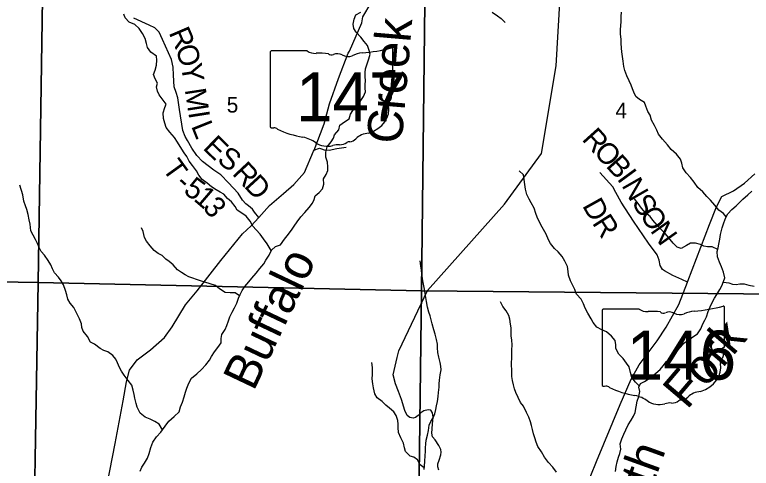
# Model space of a CAD drawing. Extents: x 2043100 to 2470832, y 443715 to 810583.
# Drawn here: x 2263711 to 2274168, y 662503 to 668947 of the extents above; entities that cross this region are included whole.
import ezdxf

# ---------------------------------------------------------------- set-up
doc = ezdxf.new("R2010")
doc.units = 0
for name, color, linetype in [('GM_X_Minor_River', 7, 'Continuous'), ('GM_X_Minor_River_Text', 7, 'Continuous'), ('GM_X_Section', 7, 'Continuous'), ('GM_X_Section_Text', 7, 'Continuous'), ('GM_X_State_Location', 7, 'Continuous'), ('GM_X_State_Route', 7, 'Continuous'), ('GM_X_State_Shield', 7, 'Continuous'), ('GM_X_Township_Road', 7, 'Continuous'), ('GM_X_Township_Road_Text', 7, 'Continuous'), ('GM_X_Township_ROW', 7, 'Continuous')]:
    doc.layers.add(name, color=color, linetype=linetype)

msp = doc.modelspace()

# ---------------------------------------------------------------- linework, layer by layer
at = {"layer": 'GM_X_Minor_River'}
for points in [[(2267354, 665598), (2267295, 665691), (2267242, 665765), (2267196, 665827), (2267137, 665892), (2267092, 665944), (2267052, 666013), (2266999, 666083), (2266935, 666128), (2266868, 666170), (2266842, 666224), (2266791, 666289), (2266732, 666335), (2266678, 666398), (2266626, 666428), (2266569, 666459), (2266507, 666503), (2266442, 666554), (2266374, 666607), (2266325, 666669), (2266293, 666727), (2266236, 666804), (2266189, 666864), (2266154, 666932), (2266116, 666983), (2266061, 667073), (2266024, 667135), (2265980, 667202), (2265911, 667278), (2265862, 667343), (2265842, 667407), (2265823, 667471), (2265820, 667555), (2265841, 667627), (2265859, 667678), (2265762, 667809), (2265739, 667863), (2265724, 667921), (2265738, 667973), (2265703, 668037), (2265683, 668098), (2265704, 668157), (2265723, 668231), (2265728, 668301), (2265726, 668359), (2265645, 668413), (2265597, 668482), (2265582, 668536), (2265561, 668608), (2265527, 668678), (2265478, 668753), (2265415, 668807), (2265337, 668842), (2265280, 668901), (2265262, 668955)], [(2267678, 665942), (2267722, 666006), (2267775, 666075), (2267832, 666138), (2267889, 666206), (2267941, 666271), (2267962, 666321), (2267978, 666374), (2268035, 666422), (2268079, 666475), (2268098, 666541), (2268095, 666613), (2268133, 666676), (2268158, 666732), (2268155, 666784), (2268153, 666850), (2268130, 666922), (2268127, 666992), (2268146, 667070), (2268206, 667139), (2268235, 667192), (2268253, 667242), (2268314, 667312), (2268329, 667377), (2268393, 667423), (2268458, 667470), (2268480, 667535), (2268511, 667587), (2268568, 667656), (2268614, 667716), (2268661, 667783), (2268690, 667851), (2268686, 667903), (2268685, 667953), (2268693, 668013), (2268688, 668066), (2268684, 668124), (2268691, 668176), (2268712, 668236), (2268737, 668322), (2268755, 668385), (2268744, 668437), (2268720, 668508), (2268671, 668568), (2268624, 668630), (2268558, 668699), (2268525, 668751), (2268516, 668813), (2268528, 668883), (2268553, 668945), (2268623, 668982)], [(2270490, 668984), (2270567, 668930), (2270619, 668895), (2270672, 668837)], [(2273811, 666077), (2273773, 666123), (2273708, 666172), (2273651, 666242), (2273591, 666311), (2273538, 666365), (2273481, 666432), (2273411, 666494), (2273358, 666567), (2273303, 666635), (2273243, 666702), (2273196, 666770), (2273183, 666840), (2273165, 666896), (2273108, 666967), (2273033, 667031), (2272977, 667100), (2272906, 667178), (2272851, 667251), (2272825, 667307), (2272794, 667375), (2272753, 667451), (2272732, 667522), (2272698, 667574), (2272671, 667646), (2272651, 667698), (2272582, 667743), (2272528, 667785), (2272499, 667845), (2272481, 667896), (2272462, 667948), (2272436, 668010), (2272403, 668078), (2272372, 668156), (2272358, 668212), (2272349, 668286), (2272338, 668352), (2272329, 668418), (2272325, 668472), (2272320, 668544), (2272320, 668594), (2272309, 668676), (2272310, 668730), (2272321, 668850), (2272322, 668924), (2272324, 668982)], [(2272580, 663669), (2272526, 663726), (2272471, 663795), (2272454, 663865), (2272433, 663943), (2272397, 663995), (2272350, 664063), (2272290, 664122), (2272245, 664204), (2272244, 664258), (2272236, 664316), (2272183, 664382), (2272114, 664443), (2272046, 664468), (2271976, 664506), (2271923, 664573), (2271895, 664627), (2271846, 664705), (2271811, 664776), (2271786, 664838), (2271752, 664904), (2271689, 664976), (2271662, 665043), (2271632, 665111), (2271603, 665167), (2271574, 665245), (2271570, 665299), (2271557, 665371), (2271520, 665447), (2271482, 665514), (2271427, 665580), (2271376, 665625), (2271316, 665697), (2271289, 665749), (2271256, 665831), (2271220, 665896), (2271179, 665962), (2271126, 666070), (2271111, 666124), (2271085, 666197), (2271044, 666273), (2271015, 666327), (2270981, 666393), (2270964, 666469), (2270951, 666537), (2270944, 666605), (2270932, 666673), (2270873, 666730)], [(2265808, 663049), (2265760, 663129), (2265698, 663167), (2265633, 663202), (2265561, 663228), (2265494, 663285), (2265450, 663369), (2265433, 663425), (2265418, 663497), (2265408, 663551), (2265395, 663611), (2265372, 663684), (2265320, 663750), (2265265, 663828), (2265226, 663881), (2265198, 663933), (2265169, 663999), (2265145, 664053), (2265102, 664104), (2265033, 664158), (2264977, 664177), (2264925, 664207), (2264846, 664268), (2264786, 664297), (2264743, 664373), (2264685, 664449), (2264662, 664505), (2264657, 664555), (2264629, 664624), (2264590, 664710), (2264551, 664788), (2264500, 664851), (2264466, 664905), (2264451, 664967), (2264431, 665027), (2264402, 665107), (2264371, 665165), (2264333, 665216), (2264278, 665278), (2264246, 665336), (2264223, 665393), (2264186, 665455), (2264132, 665531), (2264087, 665582), (2264056, 665638), (2264034, 665698), (2264005, 665754), (2263971, 665814), (2263940, 665875), (2263931, 665973), (2263918, 666033), (2263900, 666107), (2263883, 666179), (2263864, 666231), (2263840, 666299), (2263825, 666387), (2263783, 666523)], [(2272241, 662459), (2272250, 662527), (2272265, 662593), (2272283, 662661), (2272304, 662714), (2272314, 662776), (2272305, 662852), (2272328, 662920), (2272359, 662989), (2272389, 663049), (2272418, 663118), (2272465, 663188), (2272497, 663245), (2272520, 663297), (2272533, 663375), (2272548, 663458), (2272570, 663524), (2272585, 663594), (2272574, 663656), (2272596, 663707), (2272652, 663735), (2272705, 663770), (2272763, 663812), (2272814, 663853), (2272876, 663904), (2272917, 663958), (2272964, 664021), (2273016, 664068), (2273067, 664118), (2273117, 664171), (2273170, 664229), (2273212, 664280), (2273265, 664317), (2273337, 664371), (2273404, 664414), (2273450, 664483), (2273479, 664553), (2273508, 664606), (2273530, 664656), (2273555, 664732), (2273582, 664795), (2273608, 664847), (2273647, 664920), (2273678, 664972), (2273720, 665041), (2273749, 665097), (2273776, 665155), (2273792, 665208), (2273773, 665290), (2273746, 665363), (2273716, 665429), (2273687, 665505), (2273686, 665583), (2273698, 665637), (2273707, 665688), (2273722, 665756), (2273732, 665824), (2273753, 665918), (2273778, 665989), (2273805, 666065), (2273833, 666116), (2273890, 666178), (2273953, 666233), (2274050, 666326), (2274120, 666389), (2274177, 666442)], [(2273692, 665610), (2273615, 665649), (2273547, 665650), (2273495, 665657), (2273445, 665683), (2273377, 665700), (2273303, 665699), (2273247, 665667), (2273172, 665626), (2273114, 665643), (2273061, 665701), (2272952, 665832), (2272889, 665897), (2272833, 665957), (2272772, 666028), (2272731, 666080), (2272665, 666134), (2272610, 666199), (2272563, 666265), (2272511, 666330)], [(2265491, 662464), (2265514, 662520), (2265552, 662576), (2265595, 662647), (2265620, 662713), (2265645, 662798), (2265671, 662872), (2265722, 662949), (2265785, 663017), (2265846, 663102), (2265901, 663171), (2265975, 663240), (2266046, 663303), (2266065, 663375), (2266093, 663443), (2266118, 663516), (2266137, 663584), (2266156, 663640), (2266184, 663713), (2266221, 663785), (2266298, 663846), (2266362, 663907), (2266425, 663972), (2266474, 664040), (2266506, 664091), (2266549, 664159), (2266594, 664220), (2266642, 664284), (2266643, 664349), (2266652, 664403), (2266698, 664473), (2266721, 664530), (2266744, 664600), (2266764, 664654), (2266797, 664721), (2266832, 664783), (2266866, 664850), (2266887, 664920), (2266911, 664970), (2266942, 665031), (2266977, 665087), (2267035, 665154), (2267076, 665204), (2267139, 665273), (2267189, 665342), (2267246, 665408), (2267277, 665461), (2267323, 665533), (2267356, 665602), (2267415, 665655), (2267483, 665679), (2267540, 665756), (2267580, 665807), (2267639, 665885), (2267678, 665942)], [(2266902, 664951), (2266842, 664996), (2266772, 664995), (2266698, 665002), (2266620, 665051), (2266561, 665101), (2266487, 665124), (2266409, 665147), (2266347, 665165), (2266292, 665184), (2266240, 665202), (2266184, 665225), (2266132, 665249), (2266080, 665284), (2266021, 665324), (2265960, 665393), (2265906, 665443), (2265856, 665476), (2265805, 665524), (2265747, 665553), (2265692, 665599), (2265634, 665662), (2265581, 665732), (2265555, 665784), (2265534, 665866), (2265511, 665917)], [(2269523, 662485), (2269529, 662539), (2269532, 662599), (2269539, 662685), (2269541, 662742), (2269542, 662794), (2269546, 662850), (2269553, 662900), (2269572, 662972), (2269586, 663042), (2269595, 663117), (2269620, 663167), (2269652, 663220), (2269675, 663276), (2269691, 663338), (2269698, 663392), (2269711, 663453), (2269721, 663521), (2269728, 663579), (2269735, 663653), (2269739, 663703), (2269742, 663755), (2269753, 663830), (2269763, 663902), (2269760, 663956), (2269752, 664008), (2269731, 664080), (2269716, 664150), (2269714, 664212), (2269711, 664264), (2269700, 664334), (2269680, 664406), (2269659, 664472), (2269636, 664556), (2269623, 664610), (2269611, 664668), (2269592, 664720), (2269572, 664791), (2269555, 664871), (2269546, 664929), (2269536, 664985), (2269527, 665049), (2269510, 665143), (2269499, 665197), (2269491, 665265), (2269484, 665319), (2269476, 665381), (2269467, 665451)], [(2273773, 665149), (2273849, 665138), (2273901, 665119), (2273953, 665113), (2274007, 665122), (2274065, 665124), (2274131, 665105), (2274207, 665090)], [(2271405, 662450), (2271353, 662518), (2271290, 662583), (2271233, 662663), (2271188, 662736), (2271140, 662814), (2271115, 662874), (2271094, 662934), (2271076, 662994), (2271063, 663056), (2271048, 663110), (2271032, 663162), (2271009, 663231), (2270979, 663295), (2270932, 663385), (2270893, 663439), (2270858, 663510), (2270826, 663578), (2270807, 663632), (2270791, 663688), (2270778, 663752), (2270769, 663806), (2270767, 663874), (2270765, 663998), (2270767, 664070), (2270768, 664123), (2270769, 664183), (2270773, 664257), (2270768, 664321), (2270761, 664383), (2270760, 664497), (2270750, 664551), (2270739, 664621), (2270726, 664675), (2270690, 664741), (2270639, 664802), (2270606, 664870)], [(2269526, 662507), (2269465, 662554), (2269428, 662624), (2269378, 662662), (2269323, 662677), (2269261, 662741), (2269246, 662793), (2269230, 662859), (2269193, 662934), (2269160, 663012), (2269155, 663080), (2269155, 663130), (2269150, 663180), (2269126, 663254), (2269093, 663306), (2269031, 663355), (2268980, 663401), (2268926, 663454), (2268857, 663504), (2268822, 663562), (2268804, 663646), (2268795, 663702), (2268788, 663772), (2268790, 663836), (2268791, 663886), (2268789, 663936), (2268780, 664004)]]:
    msp.add_lwpolyline(points, dxfattribs=at)
at = {"layer": 'GM_X_Section'}
for points in [[(2264125, 670418), (2264045, 665142), (2258605, 665232), (2258713, 670510)], [(2264693, 670424), (2269548, 670345), (2269488, 665022), (2264045, 665142), (2264125, 670418)], [(2269548, 670345), (2269964, 670340), (2275177, 670269), (2275075, 664974), (2269488, 665022)], [(2264045, 665142), (2263953, 659859), (2258515, 659943), (2258605, 665232)], [(2264045, 665142), (2269488, 665022), (2269418, 659783), (2263953, 659859)], [(2275075, 664974), (2274869, 659715), (2269418, 659783), (2269488, 665022)]]:
    msp.add_lwpolyline(points, close=True, dxfattribs=at)
at = {"layer": 'GM_X_State_Route'}
for points in [[(2264990, 662104), (2265135, 662857), (2265250, 663463), (2265298, 663730), (2265339, 663897), (2265450, 664046), (2265640, 664187), (2265836, 664363), (2265946, 664513), (2266137, 664823), (2266303, 665022), (2266639, 665454), (2266946, 665834), (2267067, 665946), (2267176, 666066), (2267329, 666235), (2267527, 666407), (2267676, 666534), (2267823, 666707), (2267955, 667010), (2267960, 667022), (2268102, 667395), (2268180, 667683), (2268308, 668040), (2268447, 668401), (2268465, 668430), (2268641, 668832), (2268651, 668917), (2268773, 669118)], [(2271730, 662001), (2271972, 662598), (2272308, 663410), (2272463, 663768), (2272576, 663974), (2272832, 664313), (2272961, 664506), (2273139, 664830), (2273263, 665146), (2273268, 665159), (2273577, 665968), (2273673, 666216), (2273749, 666365), (2273915, 666445), (2274073, 666556), (2274220, 666684)]]:
    msp.add_lwpolyline(points, dxfattribs=at)
at = {"layer": 'GM_X_State_Shield'}
for p, q in [((2267337, 668414), (2267337, 667358)), ((2267864, 668432), (2267354, 668432)), ((2269077, 667906), (2269077, 668459)), ((2269077, 667906), (2269077, 667906)), ((2272050, 664745), (2272050, 663688)), ((2272576, 664763), (2272067, 664763)), ((2273790, 664236), (2273790, 664789)), ((2273790, 664236), (2273790, 664236))]:
    msp.add_line(p, q, dxfattribs=at)
for centre, major_axis, start_param, end_param in [((2267357, 668417), (20.2, 0), 1.712693, 3.28349), ((2267985, 668555), (196, 0), 4.042523, 4.731795), ((2268050, 667839), (702, 0), 1.404758, 1.657858), ((2268210, 668422), (56.4, 0), 3.836095, 5.185415), ((2268292, 668300), (117, 0), 0.950623, 2.079405), ((2268693, 668110), (371, 0), 1.699011, 2.107814), ((2268458, 669873), (1845, 0), 4.814394, 5.042369), ((2269058, 668461), (19.4, 0), 6.141152, 7.989035), ((2268444, 668467), (141, 0), 4.081561, 5.145723), ((2269073, 667865), (30, 0), 1.883978, 3.671073), ((2269057, 667904), (20.7, 0), 5.05454, 6.418171), ((2268882, 667795), (180, 0), 5.934695, 6.695948), ((2268561, 667604), (462, 0), 5.101752, 6.440018), ((2269147, 667675), (131, 0), 2.387724, 3.262537), ((2267357, 667355), (20.3, 0), 3.00124, 4.508301), ((2267360, 667463), (155, 0), 4.665946, 4.897461), ((2267392, 667297), (56, 0), 0.519207, 1.627899), ((2268099, 668246), (1333, 0), 4.195997, 4.488961), ((2268756, 667061), (253, 0), 1.647645, 2.488434), ((2267701, 666883), (417, 0), 0.823519, 1.323587), ((2268452, 667110), (39.7, 0), 1.147584, 2.315152), ((2268435, 667255), (149, 0), 4.937069, 5.64225), ((2268152, 667291), (265, 0), 4.026481, 4.996735), ((2268305, 666926), (217, 0), 1.495662, 1.94098), ((2268325, 667212), (141, 0), 4.691044, 5.507374), ((2272070, 664747), (20.2, 0), 1.712693, 3.28349), ((2272698, 664886), (196, 0), 4.042523, 4.731795), ((2272763, 664170), (702, 0), 1.404758, 1.657858), ((2273405, 664440), (371, 0), 1.699011, 2.107814), ((2273170, 666203), (1845, 0), 4.814394, 5.042369), ((2273770, 664791), (19.4, 0), 6.141152, 7.989035), ((2272922, 664752), (56.4, 0), 3.836095, 5.185415), ((2273005, 664630), (117, 0), 0.950623, 2.079405), ((2273156, 664798), (141, 0), 4.081561, 5.145723), ((2273785, 664196), (30, 0), 1.883978, 3.671073), ((2273769, 664234), (20.7, 0), 5.05454, 6.418171), ((2273595, 664126), (180, 0), 5.934695, 6.695948), ((2273859, 664005), (131, 0), 2.387724, 3.262537), ((2273273, 663935), (462, 0), 5.101752, 6.440018), ((2272070, 663686), (20.3, 0), 3.00124, 4.508301), ((2272073, 663794), (155, 0), 4.665946, 4.897461), ((2272105, 663627), (56, 0), 0.519207, 1.627899), ((2272811, 664576), (1333, 0), 4.195997, 4.488961), ((2273468, 663391), (253, 0), 1.647645, 2.488434), ((2272414, 663213), (417, 0), 0.823519, 1.323587), ((2273148, 663586), (149, 0), 4.937069, 5.64225), ((2272865, 663622), (265, 0), 4.026481, 4.996735), ((2273018, 663257), (217, 0), 1.495662, 1.94098), ((2273037, 663543), (141, 0), 4.691044, 5.507374), ((2273165, 663440), (39.7, 0), 1.147584, 2.315152)]:
    msp.add_ellipse(centre, major_axis=major_axis, ratio=0.8, start_param=start_param, end_param=end_param, dxfattribs=at)
at = {"layer": 'GM_X_Township_Road'}
for points in [[(2267176, 666066), (2267117, 666142), (2267085, 666184), (2267028, 666231), (2266990, 666261), (2266947, 666311), (2266885, 666413), (2266747, 666560), (2266638, 666670), (2266540, 666739), (2266375, 666862), (2266296, 666946), (2266225, 667052), (2266162, 667161), (2266130, 667217), (2266097, 667303), (2266051, 667602), (2266027, 667764), (2266005, 667840), (2265974, 667924), (2265965, 668088), (2265960, 668200), (2265935, 668310), (2265809, 668596), (2265760, 668698), (2265698, 668760), (2265621, 668799), (2265404, 668896)], [(2267960, 667022), (2268012, 667040), (2268038, 667053), (2268066, 667043), (2268104, 667029), (2268176, 667022), (2268286, 667044), (2268418, 667065)], [(2273263, 665146), (2273181, 665183), (2273056, 665244), (2272936, 665308), (2272906, 665328), (2272875, 665385), (2272859, 665460), (2272834, 665534), (2272707, 665701), (2272494, 666012), (2272322, 666282), (2272243, 666421), (2272204, 666501), (2272020, 666705)], [(2269732, 662476), (2269717, 662524), (2269719, 662568), (2269737, 662618), (2269762, 662696), (2269764, 662732), (2269762, 662771), (2269731, 662826), (2269678, 662906), (2269642, 662950), (2269634, 663000), (2269643, 663129), (2269650, 663227), (2269644, 663289), (2269619, 663327), (2269581, 663335), (2269521, 663320), (2269475, 663292), (2269437, 663255), (2269400, 663223), (2269366, 663215), (2269320, 663223), (2269285, 663252), (2269249, 663326), (2269203, 663478), (2269159, 663594), (2269116, 663704), (2269085, 663830), (2269141, 664076), (2269141, 664076)]]:
    msp.add_lwpolyline(points, dxfattribs=at)
at = {"layer": 'GM_X_Township_ROW'}
msp.add_lwpolyline([(2269141, 664076), (2269162, 664172), (2269571, 665029), (2270663, 666254), (2271191, 666975), (2271398, 668220), (2271455, 669202), (2271746, 670186)], dxfattribs=at)

# ---------------------------------------------------------------- texts
at = {"layer": 'GM_X_Minor_River_Text'}
for s, height, rotation, p in [('Creek', 500.1, 85.1198, (2269204, 667101)), ('Buffalo', 500.2, 64.5817, (2267103, 663586)), ('Fork', 500.2, 49.627, (2273256, 663325)), ('South', 500.2, 70.1183, (2272364, 661118))]:
    msp.add_text(s, height=height, rotation=rotation, dxfattribs=at).set_placement(p)
at = {"layer": 'GM_X_Section_Text'}
for s, p in [('5', (2266721, 667557)), ('4', (2272239, 667475))]:
    msp.add_text(s, height=221, rotation=0, dxfattribs=at).set_placement(p)
at = {"layer": 'GM_X_State_Location'}
for s, p in [('s', (2268188, 667816)), ('r', (2268188, 667816)), ('s', (2272900, 664147)), ('r', (2272900, 664147))]:
    msp.add_text(s, height=0.0000833, dxfattribs=at).set_placement(p)
for s, p in [('147', (2267835, 667743)), ('146', (2272547, 664073))]:
    msp.add_text(s, height=0.0000833, rotation=0, dxfattribs=at).set_placement(p)
at = {"layer": 'GM_X_State_Shield'}
for s, p in [('147', (2267704, 667432)), ('146', (2272400, 663763))]:
    msp.add_text(s, height=696.1, dxfattribs=at).set_placement(p)
at = {"layer": 'GM_X_Township_Road_Text'}
for s, rotation, p in [('R', 293.093, (2265894, 668693)), ('O', 288.3935, (2265988, 668472)), ('Y', 279.1605, (2266068, 668234)), ('M', 278.6999, (2266124, 667883)), ('I', 278.9483, (2266174, 667560)), ('L', 291.8344, (2266212, 667367)), ('R', 312.1009, (2271752, 667171)), ('E', 315.3705, (2266370, 667047)), ('S', 324.3681, (2266569, 666857)), ('O', 312.1036, (2271917, 666989)), ('B', 311.6394, (2272094, 666793)), ('T', 305.8122, (2265796, 666759)), ('R', 313.1948, (2266787, 666684)), ('I', 306.2392, (2272253, 666615)), ('5', 323.9344, (2266092, 666422)), ('D', 312.6219, (2266956, 666505)), ('N', 299.8054, (2272321, 666523)), ('-', 318.2685, (2265975, 666524)), ('1', 319.3869, (2266237, 666317)), ('3', 310.266, (2266368, 666205)), ('D', 299.1774, (2271763, 666235)), ('S', 303.313, (2272462, 666277)), ('O', 303.4294, (2272574, 666107)), ('R', 302.5804, (2271901, 665988)), ('N', 305.3524, (2272725, 665878))]:
    msp.add_text(s, height=300, rotation=rotation, dxfattribs=at).set_placement(p)

doc.saveas('drawing.dxf')
